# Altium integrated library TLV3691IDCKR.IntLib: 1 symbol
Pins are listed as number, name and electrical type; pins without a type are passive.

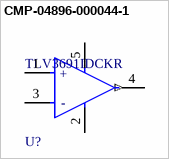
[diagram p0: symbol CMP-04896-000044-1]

## CMP-04896-000044-1
designator U?, comment TLV3691IDCKR
IC COMPARATOR NANO-POWER SC70-5; Max Supply Voltage: 6.5V; Propagation Delay: 35us; Quiescent Current: 150nA; Max Input Current: 100pA; Min Supply Voltage: 900mV; Number of Elements: 1; Min Dual Supply Voltage: 450mV; Max Dual Supply Voltage: 3.25V; Output Current: 42mA; Input Offset Voltage (Vos): 3mV; Response Time: 24us
footprint FP-DCK0005A-IPC_A
footprint FP-DCK0005A-IPC_C
footprint FP-DCK0005A-MFG
footprint FP-DCK0005A-IPC_B
pins: 1 IN+ (hiz), 2 GND (power), 3 IN- (hiz), 4 OUT (out), 5 VCC (power)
